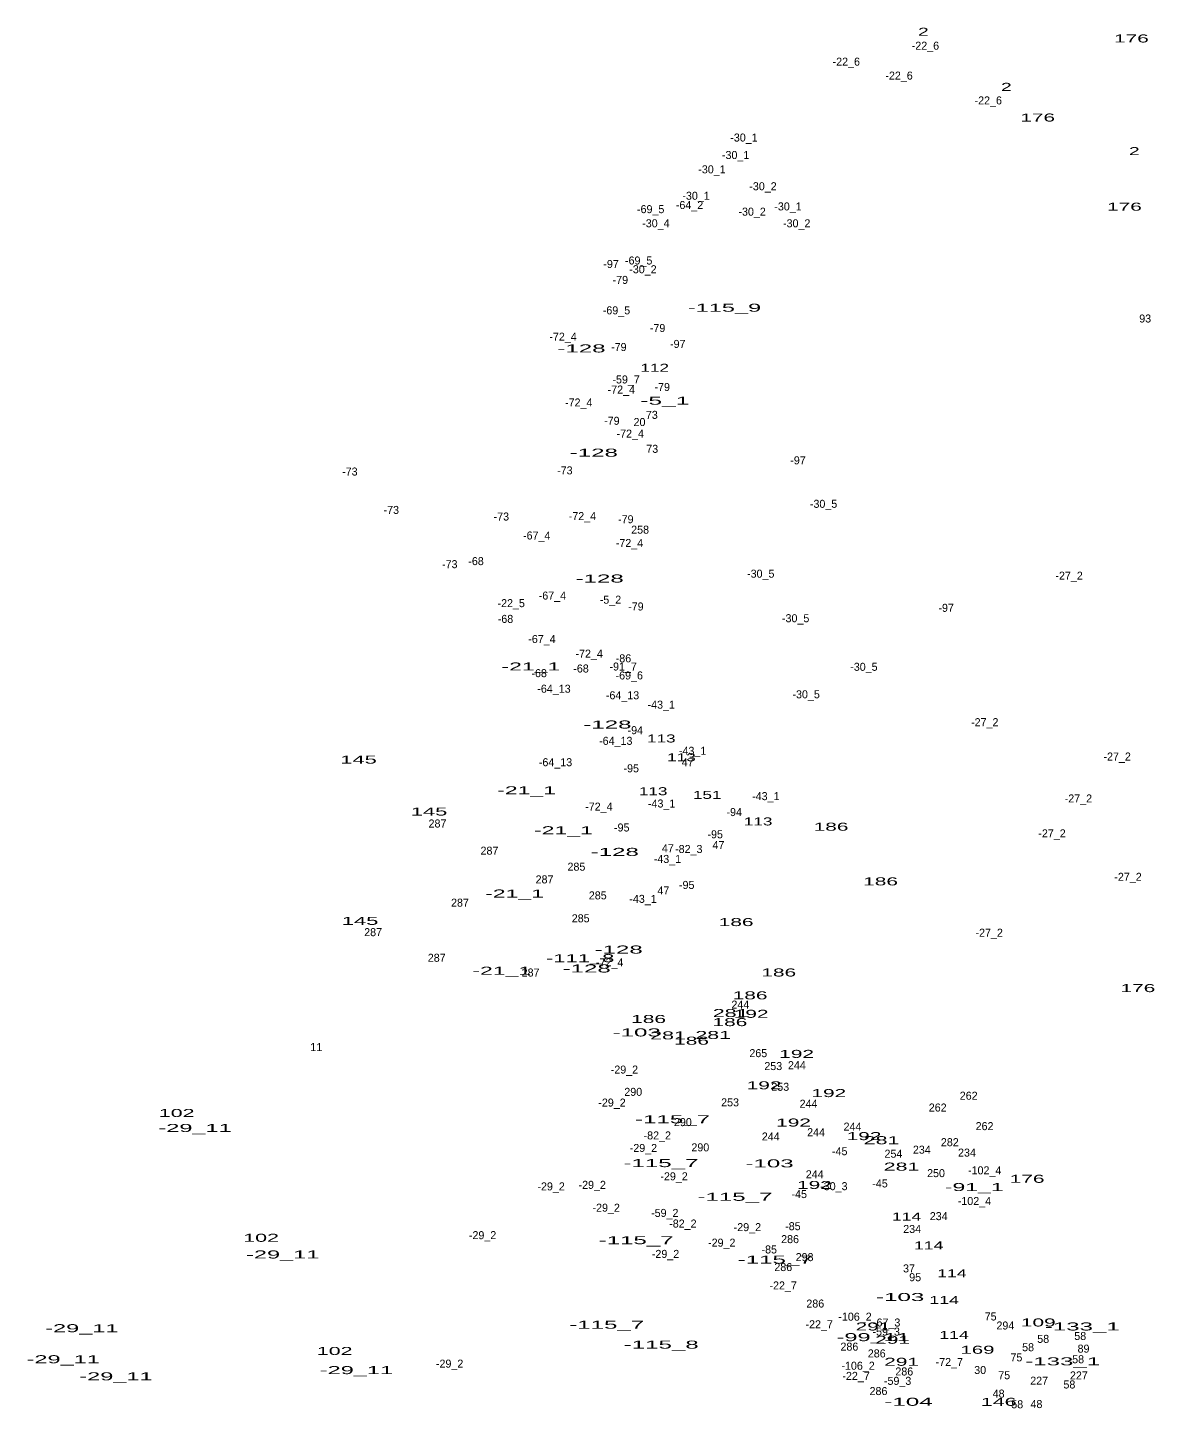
# Model space of a CAD drawing. Extents: x -656096 to -652763, y -1002270 to -998958.
# Drawn here: x -655912 to -655348, y -1000049 to -999359 of the extents above; entities that cross this region are included whole.
import ezdxf
from ezdxf.enums import TextEntityAlignment as Align

# ---------------------------------------------------------------- set-up
doc = ezdxf.new("R2010")
doc.units = 0
doc.header["$LTSCALE"] = 1.6
doc.layers.add('24', color=7, linetype='Continuous')

msp = doc.modelspace()

# ---------------------------------------------------------------- texts
at = {"layer": '24'}
for s, width, p in [('2', 1.8, (-655463.971, -999363.24)), ('176', 1.95, (-655359.977, -999366.6)), ('2', 1.8, (-655422.481, -999390.78)), ('176', 1.95, (-655406.837, -999406.12)), ('2', 1.8, (-655358.511, -999422.89)), ('176', 1.95, (-655363.467, -999450.67)), ('-115_9', 2.2, (-655563.403, -999501.16)), ('-128', 2.25, (-655634.891, -999521.49)), ('112', 1.6, (-655598.274, -999531.16)), ('-5_1', 2.3, (-655593.211, -999547.61)), ('-128', 2.25, (-655628.701, -999573.6)), ('-128', 2.25, (-655625.791, -999636.48)), ('-21_1', 2.15, (-655660.187, -999680.45)), ('-128', 2.25, (-655621.921, -999709.44)), ('113', 1.6, (-655594.984, -999716.43)), ('145', 2.05, (-655746.323, -999726.98)), ('113', 1.6, (-655584.914, -999725.81)), ('-21_1', 2.15, (-655662.317, -999742.32)), ('113', 1.6, (-655599.054, -999742.77)), ('151', 1.6, (-655572.034, -999744.6)), ('145', 2.05, (-655711.083, -999752.93)), ('113', 1.6, (-655546.574, -999757.88)), ('186', 1.95, (-655510.133, -999760.52)), ('-21_1', 2.15, (-655643.907, -999762.29)), ('-128', 2.25, (-655618.241, -999773.11)), ('186', 1.95, (-655485.353, -999787.84)), ('-21_1', 2.15, (-655668.327, -999793.9)), ('145', 2.05, (-655745.553, -999807.56)), ('186', 1.95, (-655557.573, -999808.17)), ('-128', 2.25, (-655616.301, -999821.9)), ('-111_8', 2.05, (-655635.534, -999826.21)), ('-21_1', 2.15, (-655674.727, -999832.48)), ('-128', 2.25, (-655632.281, -999831.36)), ('186', 1.95, (-655536.273, -999833.36)), ('176', 1.95, (-655356.727, -999841.16)), ('186', 1.95, (-655550.603, -999844.78)), ('186', 1.95, (-655601.333, -999856.6)), ('281', 2, (-655560.307, -999853.63)), ('186', 1.95, (-655560.673, -999858.15)), ('192', 1.95, (-655550.083, -999854.02)), ('-103', 2.25, (-655607.267, -999863.31)), ('281', 2, (-655591.617, -999864.79)), ('281', 2, (-655569.037, -999864.59)), ('11', 1.05, (-655767.454, -999870.63)), ('186', 1.95, (-655579.843, -999867.45)), ('192', 1.95, (-655527.333, -999874.06)), ('192', 1.95, (-655543.603, -999889.75)), ('192', 1.95, (-655511.263, -999893.63)), ('102', 2, (-655837.254, -999903.57)), ('-115_7', 2.25, (-655589.353, -999906.72)), ('-29_11', 2.2, (-655828.043, -999911.06)), ('192', 1.95, (-655528.883, -999908.35)), ('192', 1.95, (-655493.643, -999915.13)), ('281', 2, (-655484.867, -999917.18)), ('-115_7', 2.25, (-655595.163, -999928.61)), ('-103', 2.25, (-655540.867, -999928.76)), ('281', 2, (-655474.887, -999930.37)), ('192', 1.95, (-655518.433, -999939.54)), ('-91_1', 2.15, (-655438.543, -999940.59)), ('176', 1.95, (-655412.107, -999936.46)), ('-115_7', 2.25, (-655558.173, -999945.46)), ('114', 1.65, (-655472.359, -999955.33)), ('102', 2, (-655795.044, -999965.94)), ('-115_7', 2.25, (-655607.553, -999967.15)), ('-29_11', 2.2, (-655784.233, -999974.28)), ('114', 1.65, (-655461.319, -999969.76)), ('-115_7', 2.25, (-655538.033, -999976.84)), ('114', 1.65, (-655449.709, -999983.68)), ('-103', 2.25, (-655475.577, -999995.55)), ('114', 1.65, (-655453.579, -999997.05)), ('-115_7', 2.25, (-655622.263, -1000009.38)), ('291', 1.95, (-655489.153, -1000010.26)), ('109', 1.95, (-655406.539, -1000008.26)), ('-133_1', 2.25, (-655384.537, -1000010.26)), ('-29_11', 2.2, (-655884.653, -1000011.13)), ('-99_11', 2.2, (-655489.057, -1000015.6)), ('291', 1.95, (-655479.363, -1000016.9)), ('114', 1.65, (-655448.639, -1000014.48)), ('102', 2, (-655758.254, -1000022.5)), ('-115_8', 2.25, (-655595.017, -1000019.33)), ('169', 1.9, (-655436.917, -1000021.89)), ('-29_11', 2.2, (-655893.963, -1000026.64)), ('291', 1.95, (-655474.853, -1000027.91)), ('-133_1', 2.25, (-655394.317, -1000027.69)), ('-29_11', 2.2, (-655867.593, -1000035.18)), ('-29_11', 2.2, (-655747.393, -1000032.07)), ('-104', 2.25, (-655471.402, -1000047.89)), ('146', 2, (-655426.308, -1000047.93))]:
    msp.add_text(s, height=4, dxfattribs=dict(at, width=width)).set_placement(p, align=Align.CENTER)
for s, p in [('-22_6', (-655462.948, -999370.22)), ('-22_6', (-655502.498, -999378.18)), ('-22_6', (-655476.128, -999385.16)), ('-22_6', (-655431.538, -999397.57)), ('-30_1', (-655553.66, -999416.11)), ('-30_1', (-655557.82, -999424.84)), ('-30_1', (-655569.65, -999432.01)), ('-30_2', (-655544.146, -999440.45)), ('-64_2', (-655580.862, -999449.83)), ('-30_1', (-655577.6, -999445.2)), ('-30_1', (-655531.65, -999450.53)), ('-69_5', (-655600.283, -999451.9)), ('-30_2', (-655549.576, -999453.15)), ('-30_4', (-655597.681, -999458.96)), ('-30_2', (-655527.286, -999458.97)), ('-69_5', (-655606.283, -999477.56)), ('-97', (-655620.085, -999479.3)), ('-30_2', (-655604.156, -999481.93)), ('-79', (-655615.445, -999487.25)), ('-69_5', (-655617.393, -999502.46)), ('93', (-655353.083, -999506.55)), ('-79', (-655596.835, -999511.3)), ('-72_4', (-655644.092, -999515.63)), ('-97', (-655586.745, -999519.25)), ('-79', (-655616.215, -999520.8)), ('-59_7', (-655612.574, -999537)), ('-79', (-655594.505, -999540.78)), ('-72_4', (-655614.952, -999542.04)), ('-72_4', (-655636.252, -999548.51)), ('73', (-655599.713, -999554.7)), ('-79', (-655619.705, -999557.65)), ('20', (-655605.881, -999558.29)), ('-72_4', (-655610.502, -999564.08)), ('73', (-655599.513, -999571.67)), ('-73', (-655643.201, -999582.45)), ('-97', (-655526.645, -999577.43)), ('-73', (-655750.661, -999583.03)), ('-73', (-655729.951, -999602.21)), ('-30_5', (-655513.856, -999599.15)), ('-73', (-655674.951, -999605.5)), ('-72_4', (-655634.412, -999605.29)), ('-79', (-655612.725, -999606.86)), ('-67_4', (-655657.248, -999614.99)), ('258', (-655605.577, -999612.07)), ('-72_4', (-655610.892, -999618.74)), ('-73', (-655700.711, -999629.32)), ('-68', (-655687.59, -999627.8)), ('-30_5', (-655545.266, -999634.06)), ('-27_2', (-655391.128, -999635.07)), ('-22_5', (-655670.012, -999648.8)), ('-67_4', (-655649.408, -999645.01)), ('-5_2', (-655620.393, -999647.06)), ('-79', (-655607.685, -999650.45)), ('-97', (-655452.585, -999651.13)), ('-68', (-655672.87, -999656.66)), ('-30_5', (-655527.816, -999656.33)), ('-67_4', (-655654.638, -999666.71)), ('-72_4', (-655631.032, -999674.04)), ('-86', (-655613.9, -999676.37)), ('-68', (-655656.03, -999683.78)), ('-68', (-655635.11, -999681.45)), ('-91_7', (-655614.047, -999680.47)), ('-69_6', (-655610.998, -999684.92)), ('-30_5', (-655493.696, -999680.6)), ('-64_13', (-655648.626, -999691.55)), ('-64_13', (-655614.356, -999694.84)), ('-43_1', (-655595.01, -999699.53)), ('-30_5', (-655522.576, -999694.34)), ('-94', (-655607.965, -999712.27)), ('-27_2', (-655433.278, -999708.27)), ('-64_13', (-655617.746, -999717.6)), ('-43_1', (-655579.32, -999722.58)), ('-27_2', (-655367.088, -999725.44)), ('-64_13', (-655647.856, -999728.29)), ('-95', (-655610, -999731.33)), ('47', (-655581.817, -999728.3)), ('-43_1', (-655542.73, -999745.24)), ('-27_2', (-655386.478, -999746.39)), ('-72_4', (-655626.192, -999750.48)), ('-43_1', (-655594.81, -999748.92)), ('-94', (-655558.525, -999753.19)), ('287', (-655706.863, -999758.91)), ('-95', (-655614.75, -999760.9)), ('-95', (-655568.03, -999764.3)), ('-27_2', (-655399.658, -999763.84)), ('287', (-655680.883, -999772.49)), ('47', (-655591.707, -999771.25)), ('-82_3', (-655581.242, -999771.65)), ('47', (-655566.407, -999769.69)), ('285', (-655637.407, -999780.49)), ('-43_1', (-655591.91, -999776.62)), ('287', (-655653.353, -999786.84)), ('-27_2', (-655361.668, -999785.56)), ('285', (-655626.747, -999794.84)), ('47', (-655593.937, -999792.39)), ('-95', (-655582.28, -999789.61)), ('287', (-655695.623, -999798.47)), ('-43_1', (-655604.11, -999796.57)), ('285', (-655635.277, -999806.28)), ('287', (-655739.043, -999813.21)), ('-27_2', (-655431.068, -999813.49)), ('287', (-655707.253, -999826.01)), ('-72_4', (-655620.772, -999828.29)), ('287', (-655660.333, -999833.38)), ('244', (-655555.466, -999849.41)), ('265', (-655546.503, -999873.68)), ('-29_2', (-655613.418, -999881.88)), ('253', (-655539.007, -999880.13)), ('244', (-655527.196, -999879.68)), ('290', (-655609.007, -999893.01)), ('253', (-655535.517, -999890.49)), ('-29_2', (-655619.618, -999898.37)), ('253', (-655560.597, -999898.24)), ('244', (-655521.386, -999898.95)), ('262', (-655441.323, -999894.94)), ('262', (-655456.813, -999900.85)), ('290', (-655584.197, -999908.14)), ('244', (-655517.606, -999913.19)), ('244', (-655499.406, -999910.38)), ('262', (-655433.383, -999910.15)), ('-82_2', (-655596.992, -999914.79)), ('244', (-655540.266, -999915.32)), ('282', (-655450.757, -999918.17)), ('-29_2', (-655603.918, -999921.06)), ('290', (-655575.467, -999920.75)), ('-45', (-655505.789, -999922.69)), ('254', (-655478.931, -999923.93)), ('234', (-655464.741, -999921.91)), ('234', (-655442.181, -999923.37)), ('244', (-655518.286, -999934.21)), ('250', (-655457.651, -999933.63)), ('-102_4', (-655433.314, -999932.24)), ('-29_2', (-655650.058, -999940.26)), ('-29_2', (-655629.508, -999939.48)), ('-29_2', (-655588.598, -999935.22)), ('-30_3', (-655508.716, -999940.15)), ('-45', (-655485.649, -999938.77)), ('-45', (-655526.019, -999944.1)), ('-102_4', (-655438.444, -999947.56)), ('-29_2', (-655622.528, -999950.92)), ('-59_2', (-655593.238, -999953.52)), ('-82_2', (-655584.192, -999958.82)), ('-29_2', (-655551.958, -999960.62)), ('-85', (-655529.195, -999960.15)), ('234', (-655469.581, -999961.53)), ('234', (-655456.311, -999955.13)), ('-29_2', (-655684.318, -999964.63)), ('-29_2', (-655564.758, -999968.38)), ('286', (-655530.613, -999966.61)), ('-29_2', (-655592.868, -999974)), ('-85', (-655541.015, -999971.78)), ('298', (-655523.353, -999975.6)), ('286', (-655534.003, -999980.58)), ('37', (-655471.153, -999981.25)), ('95', (-655468.083, -999985.64)), ('-22_7', (-655534.068, -999989.77)), ('286', (-655518.013, -999998.81)), ('-22_7', (-655516.038, -1000009.16)), ('-106_2', (-655498.156, -1000005.37)), ('-67_3', (-655482.324, -1000008.28)), ('75', (-655430.343, -1000005.25)), ('294', (-655422.977, -1000009.77)), ('-59_3', (-655482.558, -1000012.83)), ('58', (-655404.067, -1000016.46)), ('58', (-655385.557, -1000015.01)), ('286', (-655500.953, -1000020.33)), ('286', (-655487.283, -1000023.73)), ('58', (-655411.627, -1000020.63)), ('89', (-655383.913, -1000021.33)), ('-29_2', (-655700.798, -1000028.83)), ('-106_2', (-655496.606, -1000029.88)), ('-72_7', (-655451.004, -1000028.01)), ('75', (-655417.463, -1000025.7)), ('58', (-655386.617, -1000026.64)), ('-22_7', (-655497.618, -1000034.96)), ('-59_3', (-655476.848, -1000037.43)), ('286', (-655473.513, -1000032.75)), ('30', (-655435.581, -1000032.01)), ('75', (-655423.563, -1000034.62)), ('227', (-655406.093, -1000037.34)), ('227', (-655386.243, -1000034.72)), ('286', (-655486.413, -1000042.54)), ('48', (-655426.341, -1000043.8)), ('58', (-655390.977, -1000039.25)), ('58', (-655417.057, -1000049.14)), ('48', (-655407.441, -1000049.04))]:
    msp.add_text(s, height=4, dxfattribs=at).set_placement(p, align=Align.CENTER)

doc.saveas('drawing.dxf')
